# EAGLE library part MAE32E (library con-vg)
CONNECTOR male, 32 pins, single, type E, rows AE, grid 10.16
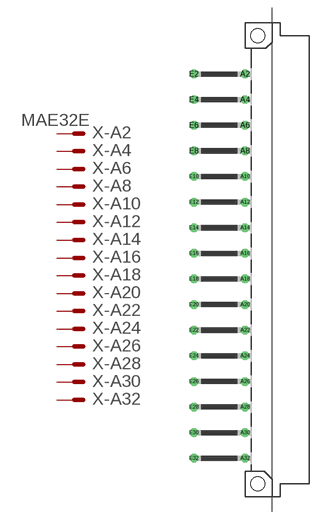
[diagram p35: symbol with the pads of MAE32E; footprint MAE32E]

Designator prefix X; gates -A2=MVAL -A4=MAL -A6=MAL -A8=MAL -A10=MAL -A12=MAL -A14=MAL -A16=MAL -A18=MAL -A20=MAL -A22=MAL -A24=MAL -A26=MAL -A28=MAL -A30=MAL -A32=MAL -E2=MVAL -E4=MAL -E6=MAL -E8=MAL -E10=MAL -E12=MAL -E14=MAL -E16=MAL -E18=MAL -E20=MAL -E22=MAL -E24=MAL -E26=MAL -E28=MAL -E30=MAL -E32=MAL

## MAE32E  [MAE32E]
A2  -A2:S  pas
A4  -A4:S  pas
A6  -A6:S  pas
A8  -A8:S  pas
A10  -A10:S  pas
A12  -A12:S  pas
A14  -A14:S  pas
A16  -A16:S  pas
A18  -A18:S  pas
A20  -A20:S  pas
A22  -A22:S  pas
A24  -A24:S  pas
A26  -A26:S  pas
A28  -A28:S  pas
A30  -A30:S  pas
A32  -A32:S  pas
E2  -E2:S  pas
E4  -E4:S  pas
E6  -E6:S  pas
E8  -E8:S  pas
E10  -E10:S  pas
E12  -E12:S  pas
E14  -E14:S  pas
E16  -E16:S  pas
E18  -E18:S  pas
E20  -E20:S  pas
E22  -E22:S  pas
E24  -E24:S  pas
E26  -E26:S  pas
E28  -E28:S  pas
E30  -E30:S  pas
E32  -E32:S  pas

## Footprint MAE32E (pad centres in mm)
CONNECTOR male, 32 pins, type E, rows AE, grid 10.16
drill 1.118 octagon: A2 -2.54,36.83; A4 -2.54,31.75; A6 -2.54,26.67; A8 -2.54,21.59; A10 -2.54,16.51; A12 -2.54,11.43; A14 -2.54,6.35; A16 -2.54,1.27; A18 -2.54,-3.81; A20 -2.54,-8.89; A22 -2.54,-13.97; A24 -2.54,-19.05; A26 -2.54,-24.13; A28 -2.54,-29.21; A30 -2.54,-34.29; A32 -2.54,-39.37; E2 -12.7,36.83; E4 -12.7,31.75; E6 -12.7,26.67; E8 -12.7,21.59; E10 -12.7,16.51; E12 -12.7,11.43; E14 -12.7,6.35; E16 -12.7,1.27; E18 -12.7,-3.81; E20 -12.7,-8.89; E22 -12.7,-13.97; E24 -12.7,-19.05; E26 -12.7,-24.13; E28 -12.7,-29.21; E30 -12.7,-34.29; E32 -12.7,-39.37
hole 2.794 at 0,44.45
hole 2.794 at 0,-44.45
